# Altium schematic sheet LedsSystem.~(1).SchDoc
size A4
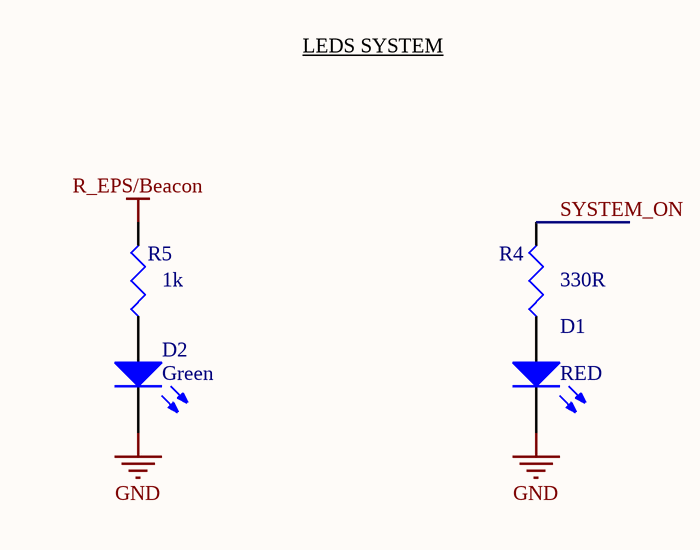
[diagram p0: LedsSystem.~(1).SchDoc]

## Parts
D1  RED  [3.2X1.6X1.1]
D2  Green  [3.2X1.6X1.1]
R4  value 330R  [J1-0603]  (hidden comment: Res3)
R5  value 1k  [J1-0603]  (hidden comment: Res3)

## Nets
GND: D1.2(K) D2.2(K)
R_EPS/Beacon: R5.2
SYSTEM_ON: R4.2

Not connected (* = marked no-connect by the designer): D1 1(A); D2 1(A); R4 1; R5 1

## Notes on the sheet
- LEDS SYSTEM

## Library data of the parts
D1 D2 = LED2: Typical RED, GREEN, YELLOW, AMBER GaAs LED
R4 R5 = Res3: Resistor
